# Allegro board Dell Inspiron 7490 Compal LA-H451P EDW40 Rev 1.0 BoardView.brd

Outline 215.71 x 81.8 mm; copper layers: TOP, GND1, IN1, GND2, VCC, IN2, GND3, IN3, GND4, BOTTOM. Coordinates in mm from the lower left corner of the outline.
Outline path: circle c80.48,25.78 r0.65 ; 0,29.9 0,15.1 0.6,14.5 0.6,0 16.6,0 arc(17.19,1.41) 18.6,2 27.15,2 27.15,3 arc(27.3,3.35) 27.65,3.5 29.45,3.5 arc(29.8,3.35) 29.95,3 29.95,2 46.15,2 46.15,3 arc(46.3,3.35) 46.65,3.5 48.45,3.5 arc(48.8,3.35) 48.95,3 48.95,2 215.71,2 215.71,5.2 214.95,5.2 arc(213.15,7) 214.95,8.8 215.71,8.8 215.71,17.38 arc(213.29,21.9) 211.59,26.73 206.19,46.9 203.75,46.9 arc(201.65,49) 203.75,51.1 205.06,51.1 200.21,69.21 200.21,81.8 165.35,81.8 165.35,81 arc(165.2,80.65) 164.85,80.5 163.05,80.5 arc(162.7,80.65) 162.55,81 162.55,81.8 75.45,81.8 75.45,81 arc(75.3,80.65) 74.95,80.5 73.15,80.5 arc(72.8,80.65) 72.65,81 72.65,81.8 49.95,81.8 49.95,81 arc(49.8,80.65) 49.45,80.5 47.65,80.5 arc(47.3,80.65) 47.15,81 47.15,81.8 24.4,81.8 20.6,78 0.6,78 0.6,70.65 5.96,70.65 arc(6.46,71.14) 6.96,70.65 6.96,61.35 arc(6.46,60.85) 5.96,61.35 1.36,61.35 arc(0.99,60.89) 0.82,60.32 arc(0.72,60.13) 0.52,60.05 0.4,60.05 arc(0.19,59.96) 0.1,59.75 0.1,59.45 arc(0.19,59.24) 0.4,59.15 1.25,59.15 arc(1.6,59) 1.75,58.65 1.75,54.45 arc(1.66,54.24) 1.45,54.15 0.6,54.15 arc(0.39,54.06) 0.3,53.85 0.3,52.75 arc(0.39,52.54) 0.6,52.45 1.2,52.45 arc(1.41,52.36) 1.5,52.15 1.5,51.25 10.31,51.25 arc(10.81,50.75) 10.31,50.25 10.31,36.75 arc(10.81,36.25) 10.31,35.75 0.6,35.75 0.6,30.5 0,29.9 ; 11.25,76.9 arc(11.6,77.25) 11.95,76.9 11.95,74.1 arc(11.6,73.75) 11.25,74.1 11.25,76.9 ; 11.25,57.9 arc(11.6,58.25) 11.95,57.9 11.95,55.1 arc(11.6,54.75) 11.25,55.1 11.25,57.9 ; 115.4,79.3 arc(115.49,79.51) 115.7,79.6 116,79.6 arc(116.21,79.51) 116.3,79.3 116.3,78 arc(116.21,77.79) 116,77.7 115.7,77.7 arc(115.49,77.79) 115.4,78 115.4,79.3

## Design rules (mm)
constraint set DEFAULT: min track width 0.081
net group CLK_ITPXDP_: nets CLK_ITPXDP_N CLK_ITPXDP_P
net group CLK_ITPXDP__R: nets CLK_ITPXDP_N_R CLK_ITPXDP_P_R
net group CLK_TP_SIO_I2C_DAT: nets CLK_TP_SIO_I2C_DAT DAT_TP_SIO_I2C_CLK
net group DIFFPAIR0: nets DDR_M1_CLK0 DDR_M1_CLK#0
net group DIFFPAIR1: nets DDR_M1_DQS7 DDR_M1_DQS#7
net group DIFFPAIR2: nets DDR_M0_DQS5 DDR_M0_DQS#5
net group DIFFPAIR3: nets DDR_M0_DQS4 DDR_M0_DQS#4
net group DIFFPAIR4: nets DDR_M0_DQS1 DDR_M0_DQS#1
net group DIFFPAIR5: nets DDR_M0_DQS0 DDR_M0_DQS#0
net group DIFFPAIR6: nets DDR_M0_DQS3 DDR_M0_DQS#3
net group DIFFPAIR7: nets DDR_M1_DQS6 DDR_M1_DQS#6
net group DIFFPAIR8: nets DDR_M1_DQS3 DDR_M1_DQS#3
net group DIFFPAIR9: nets DDR_M1_DQS2 DDR_M1_DQS#2
net group DIFFPAIR10: nets DDR_M0_DQS7 DDR_M0_DQS#7
net group DIFFPAIR11: nets DDR_M0_DQS6 DDR_M0_DQS#6
net group DIFFPAIR12: nets DDR_M0_DQS2 DDR_M0_DQS#2
net group DIFFPAIR13: nets DDR_M1_DQS0 DDR_M1_DQS#0
net group DIFFPAIR14: nets DDR_M1_DQS1 DDR_M1_DQS#1
net group DIFFPAIR15: nets DDR_M1_DQS4 DDR_M1_DQS#4
net group DIFFPAIR16: nets DDR_M1_DQS5 DDR_M1_DQS#5
net group DIFFPAIR34: nets DDR_M0_CLK1 DDR_M0_CLK#1
net group DIFFPAIR35: nets DDR_M0_CLK0 DDR_M0_CLK#0
net group DIFFPAIR36: nets DDR_M1_CLK1 DDR_M1_CLK#1
net group DIFFPAIR37: nets XTAL_IN XTAL_OUT
net group DIFFPAIR53: nets NCT7718_DXN NCT7718_DXP
net group DIFFPAIR54: nets PRB12_CSON PRB12_CSOP
net group DIFFPAIR55: nets PRB01_CSIN PRB01_CSIP
net group DIFFPAIR56: nets GND_SENSE_GPU VDD_SENSE_GPU
net group DIFFPAIR57: nets DMIC_CLK_EDP DMIC_DATA_EDP
net group DIFFPAIR58: nets PBAT_CHARGER_SMBCLK PBAT_CHARGER_SMBDAT
net group DIFFPAIR59: nets TBT_DP1_N3_R TBT_DP1_P3_R
net group DIFFPAIR60: nets TBT_DP1_N2_R TBT_DP1_P2_R
net group DIFFPAIR61: nets TBT_DP1_N1_R TBT_DP1_P1_R
net group DIFFPAIR62: nets TBT_DP1_N0_R TBT_DP1_P0_R
net group LED: nets AMBER_LED_BAT WHITE_LED_BAT
net group SMB: nets GPU_THM_SMBCLK GPU_THM_SMBDAT
net group ASY: nets ALL_SYS_PWRGD CATERR# H_CPUPWRGD H_PROCHOT# H_PROCHOT#_R H_THERMTRIP# PECI_EC RUNPWROK SCLK_CPU SDIO_CPU VCCST_PWRGD VIDALERT# VIDSCLK VIDSOUT
net group AUDIO: nets DMIC_CLK0 DMIC_CLK_CODEC DMIC_DATA0 DMIC_DATA_CODEC
net group CARD: nets SD_WP
net group CLK: nets REFCLK_CNV REFCLK_CNV_L REFCLK_CNV_R XCLK_BIASREF XTAL_OUTBUFF XTAL_SSIN
net group CLK_RT-24M: nets PCH_RTCX1 PCH_RTCX2 XTAL24_IN XTAL24_IN_R XTAL24_OUT XTAL24_OUT_R
net group CNVI_12_15: nets CLK_CNV_CRX_DTX_N CLK_CNV_CRX_DTX_P CLK_CNV_CRX_R_DTX_N CLK_CNV_CRX_R_DTX_P CLK_CNV_CTX_DRX_N CLK_CNV_CTX_DRX_P CLK_CNV_CTX_R_DRX_N CLK_CNV_CTX_R_DRX_P CNV_CRX_DTX_N0 CNV_CRX_DTX_N1 CNV_CRX_DTX_P0 CNV_CRX_DTX_P1 CNV_CRX_R_DTX_N0 CNV_CRX_R_DTX_N1 CNV_CRX_R_DTX_P0 CNV_CRX_R_DTX_P1 CNV_CTX_DRX_N0 CNV_CTX_DRX_N1 CNV_CTX_DRX_P0 CNV_CTX_DRX_P1 CNV_CTX_R_DRX_N0 CNV_CTX_R_DRX_N1 CNV_CTX_R_DRX_P0 CNV_CTX_R_DRX_P1
net group CNVIRGI-BRI_5_15: nets CNV_BRI_CRX_DTX CNV_BRI_CRX_R_DTX CNV_BRI_CTX_DRX CNV_BRI_CTX_R_DRX CNV_RGI_CRX_DTX CNV_RGI_CRX_R_DTX CNV_RGI_CTX_DRX CNV_RGI_CTX_R_DRX
net group CPU_SPI: nets CPU_SPI_0_CLK CPU_SPI_0_CS#0 CPU_SPI_0_CS#1 CPU_SPI_0_D0 CPU_SPI_0_D1 CPU_SPI_0_D2 CPU_SPI_0_D3 CPU_SPI_CLK CPU_SPI_D0 CPU_SPI_D1 CPU_SPI_D2 CPU_SPI_D3 SPI_CLK_ROM SPI_D0_ROM SPI_D1_ROM SPI_D2_ROM SPI_D3_ROM
net group DDRA_CKE: nets DDR_M0_CKE0 DDR_M0_CKE1 DDR_M0_CKE2 DDR_M0_CKE3
net group DDRA_CMD: nets DDR_M0_CAA_0 DDR_M0_CAA_1 DDR_M0_CAA_2 DDR_M0_CAA_3 DDR_M0_CAA_4 DDR_M0_CAA_5 DDR_M0_CAA_6 DDR_M0_CAA_7 DDR_M0_CAA_8 DDR_M0_CAA_9 DDR_M0_CAB_0 DDR_M0_CAB_1 DDR_M0_CAB_2 DDR_M0_CAB_3 DDR_M0_CAB_4 DDR_M0_CAB_5 DDR_M0_CAB_6 DDR_M0_CAB_7 DDR_M0_CAB_8 DDR_M0_CAB_9
net group DDRA_CTRL: nets DDR_M0_CS#0 DDR_M0_CS#1 DDR_M0_ODT0
net group DDRA_DS0: nets DDR_M0_D0 DDR_M0_D1 DDR_M0_D2 DDR_M0_D3 DDR_M0_D4 DDR_M0_D5 DDR_M0_D6 DDR_M0_D7
net group DDRA_DS1: nets DDR_M0_D8 DDR_M0_D9 DDR_M0_D10 DDR_M0_D11 DDR_M0_D12 DDR_M0_D13 DDR_M0_D14 DDR_M0_D15
net group DDRA_DS2: nets DDR_M0_D16 DDR_M0_D17 DDR_M0_D18 DDR_M0_D19 DDR_M0_D20 DDR_M0_D21 DDR_M0_D22 DDR_M0_D23
net group DDRA_DS3: nets DDR_M0_D24 DDR_M0_D25 DDR_M0_D26 DDR_M0_D27 DDR_M0_D28 DDR_M0_D29 DDR_M0_D30 DDR_M0_D31
net group DDRA_DS4: nets DDR_M0_D32 DDR_M0_D33 DDR_M0_D34 DDR_M0_D35 DDR_M0_D36 DDR_M0_D37 DDR_M0_D38 DDR_M0_D39
net group DDRA_DS5: nets DDR_M0_D40 DDR_M0_D41 DDR_M0_D42 DDR_M0_D43 DDR_M0_D44 DDR_M0_D45 DDR_M0_D46 DDR_M0_D47
net group DDRA_DS6: nets DDR_M0_D48 DDR_M0_D49 DDR_M0_D50 DDR_M0_D51 DDR_M0_D52 DDR_M0_D53 DDR_M0_D54 DDR_M0_D55
net group DDRA_DS7: nets DDR_M0_D56 DDR_M0_D57 DDR_M0_D58 DDR_M0_D59 DDR_M0_D60 DDR_M0_D61 DDR_M0_D62 DDR_M0_D63
net group DDRB_CKE: nets DDR_M1_CKE0 DDR_M1_CKE1 DDR_M1_CKE2 DDR_M1_CKE3
net group DDRB_CMD: nets DDR_M1_CAA_0 DDR_M1_CAA_1 DDR_M1_CAA_2 DDR_M1_CAA_3 DDR_M1_CAA_4 DDR_M1_CAA_5 DDR_M1_CAA_6 DDR_M1_CAA_7 DDR_M1_CAA_8 DDR_M1_CAA_9 DDR_M1_CAB_0 DDR_M1_CAB_1 DDR_M1_CAB_2 DDR_M1_CAB_3 DDR_M1_CAB_4 DDR_M1_CAB_5 DDR_M1_CAB_6 DDR_M1_CAB_7 DDR_M1_CAB_8 DDR_M1_CAB_9
net group DDRB_CTRL: nets DDR_M1_CS#0 DDR_M1_CS#1 DDR_M1_ODT0
net group DDRB_DS0: nets DDR_M1_D0 DDR_M1_D1 DDR_M1_D2 DDR_M1_D3 DDR_M1_D4 DDR_M1_D5 DDR_M1_D6 DDR_M1_D7
net group DDRB_DS1: nets DDR_M1_D8 DDR_M1_D9 DDR_M1_D10 DDR_M1_D11 DDR_M1_D12 DDR_M1_D13 DDR_M1_D14 DDR_M1_D15
net group DDRB_DS2: nets DDR_M1_D16 DDR_M1_D17 DDR_M1_D18 DDR_M1_D19 DDR_M1_D20 DDR_M1_D21 DDR_M1_D22 DDR_M1_D23
net group DDRB_DS3: nets DDR_M1_D24 DDR_M1_D25 DDR_M1_D26 DDR_M1_D27 DDR_M1_D28 DDR_M1_D29 DDR_M1_D30 DDR_M1_D31
net group DDRB_DS4: nets DDR_M1_D32 DDR_M1_D33 DDR_M1_D34 DDR_M1_D35 DDR_M1_D36 DDR_M1_D37 DDR_M1_D38 DDR_M1_D39
net group DDRB_DS5: nets DDR_M1_D40 DDR_M1_D41 DDR_M1_D42 DDR_M1_D43 DDR_M1_D44 DDR_M1_D45 DDR_M1_D46 DDR_M1_D47
net group DDRB_DS6: nets DDR_M1_D48 DDR_M1_D49 DDR_M1_D50 DDR_M1_D51 DDR_M1_D52 DDR_M1_D53 DDR_M1_D54 DDR_M1_D55
net group DDRB_DS7: nets DDR_M1_D56 DDR_M1_D57 DDR_M1_D58 DDR_M1_D59 DDR_M1_D60 DDR_M1_D61 DDR_M1_D62 DDR_M1_D63
net group DP: nets CPU_DP1_AUXN CPU_DP1_AUXN_C CPU_DP1_AUXP CPU_DP1_AUXP_C CPU_DP1_CTRL_DATA CPU_DP1_N0 CPU_DP1_N0_C CPU_DP1_N1 CPU_DP1_N1_C CPU_DP1_N2 CPU_DP1_N2_C CPU_DP1_N3 CPU_DP1_N3_C CPU_DP1_P0 CPU_DP1_P0_C CPU_DP1_P1 CPU_DP1_P1_C CPU_DP1_P2 CPU_DP1_P2_C CPU_DP1_P3 CPU_DP1_P3_C CPU_DP2_AUXN CPU_DP2_AUXN_C CPU_DP2_AUXP CPU_DP2_AUXP_C CPU_DP2_CTRL_DATA CPU_DP2_N0 CPU_DP2_N0_C CPU_DP2_N1 CPU_DP2_N1_C CPU_DP2_N2 CPU_DP2_N2_C CPU_DP2_N3 CPU_DP2_N3_C CPU_DP2_P0 CPU_DP2_P0_C CPU_DP2_P1 CPU_DP2_P1_C CPU_DP2_P2 CPU_DP2_P2_C CPU_DP2_P3 CPU_DP2_P3_C
net group EDP: nets EDP_AUXN EDP_AUXN_C EDP_AUXP EDP_AUXP_C EDP_TXN0 EDP_TXN0_C EDP_TXN1 EDP_TXN1_C EDP_TXP0 EDP_TXP0_C EDP_TXP1 EDP_TXP1_C
net group ESPI: nets ESPI_CLK ESPI_CLK_R ESPI_CS# ESPI_IO0 ESPI_IO0_R ESPI_IO1 ESPI_IO1_R ESPI_IO2 ESPI_IO2_R ESPI_IO3 ESPI_IO3_R ESPI_RESET#
net group FB_A_CLK: nets FB_A_CLK0 FB_A_CLK1 FB_A_CLK#0 FB_A_CLK#1
net group FB_A_CMD: nets FB_A_CMD0 FB_A_CMD1 FB_A_CMD2 FB_A_CMD3 FB_A_CMD4 FB_A_CMD5 FB_A_CMD6 FB_A_CMD7 FB_A_CMD8 FB_A_CMD9 FB_A_CMD10 FB_A_CMD11 FB_A_CMD12 FB_A_CMD13 FB_A_CMD14 FB_A_CMD15 FB_A_CMD16 FB_A_CMD17 FB_A_CMD18 FB_A_CMD19 FB_A_CMD20 FB_A_CMD21 FB_A_CMD22 FB_A_CMD23 FB_A_CMD24 FB_A_CMD25 FB_A_CMD26 FB_A_CMD27 FB_A_CMD28 FB_A_CMD29 FB_A_CMD30 FB_A_CMD31
net group FB_A_DBI: nets FB_A_DBI0 FB_A_DBI1 FB_A_DBI2 FB_A_DBI3 FB_A_DBI4 FB_A_DBI5 FB_A_DBI6 FB_A_DBI7
net group FB_A_DSM0: nets FB_A_D0 FB_A_D1 FB_A_D2 FB_A_D3 FB_A_D4 FB_A_D5 FB_A_D6 FB_A_D7
net group FB_A_DSM1: nets FB_A_D8 FB_A_D9 FB_A_D10 FB_A_D11 FB_A_D12 FB_A_D13 FB_A_D14 FB_A_D15
net group FB_A_DSM2: nets FB_A_D16 FB_A_D17 FB_A_D18 FB_A_D19 FB_A_D20 FB_A_D21 FB_A_D22 FB_A_D23
net group FB_A_DSM3: nets FB_A_D24 FB_A_D25 FB_A_D26 FB_A_D27 FB_A_D28 FB_A_D29 FB_A_D30 FB_A_D31
net group FB_A_DSM4: nets FB_A_D32 FB_A_D33 FB_A_D34 FB_A_D35 FB_A_D36 FB_A_D37 FB_A_D38 FB_A_D39
net group FB_A_DSM5: nets FB_A_D40 FB_A_D41 FB_A_D42 FB_A_D43 FB_A_D44 FB_A_D45 FB_A_D46 FB_A_D47
net group FB_A_DSM6: nets FB_A_D48 FB_A_D49 FB_A_D50 FB_A_D51 FB_A_D52 FB_A_D53 FB_A_D54 FB_A_D55
net group FB_A_DSM7: nets FB_A_D56 FB_A_D57 FB_A_D58 FB_A_D59 FB_A_D60 FB_A_D61 FB_A_D62 FB_A_D63
net group FB_A_EDC: nets FB_A_EDC0 FB_A_EDC1 FB_A_EDC2 FB_A_EDC3 FB_A_EDC4 FB_A_EDC5 FB_A_EDC6 FB_A_EDC7
net group FB_A_WCK: nets FB_A_WCK0 FB_A_WCK1 FB_A_WCK2 FB_A_WCK3 FB_A_WCK#0 FB_A_WCK#1 FB_A_WCK#2 FB_A_WCK#3
net group FB_VREF: nets FB_VREF
net group HDA: nets HDA_BIT_CLK HDA_BIT_CLK_R HDA_SDIN0 HDA_SDOUT HDA_SDOUT_R HDA_SYNC HDA_SYNC_R
net group HDMI: nets TMDS_T_TX0N TMDS_T_TX0N_R TMDS_T_TX0P TMDS_T_TX0P_R TMDS_T_TX1N TMDS_T_TX1N_R TMDS_T_TX1P TMDS_T_TX1P_R TMDS_T_TX2N TMDS_T_TX2N_R TMDS_T_TX2P TMDS_T_TX2P_R TMDS_T_TXCN TMDS_T_TXCN_R TMDS_T_TXCP TMDS_T_TXCP_R
net group I2C: nets DDC_SCL_HDMI DDC_SDA_HDMI I2C1_PD_L_CLK I2C1_PD_L_DAT I2C1_PD_L_INT# I2C2_PD_L_CLK I2C2_PD_L_DAT I2C2_PD_L_INT# I2C_0_SCL I2C_0_SDA I2C_1_SCL I2C_1_SDA I2CB_SCL I2CB_SDA I2CC_SCL I2CC_SDA I2CS_SCL I2CS_SDA ISH_I2C_0_SCL ISH_I2C_0_SDA ISH_I2C_1_SCL ISH_I2C_1_SDA PS_SMBCLK PS_SMBDAT TBT_I2C_SCL TBT_I2C_SDA TBTA_I2C_INT#
net group KB: nets KSI0 KSI1 KSI2 KSI3 KSI4 KSI5 KSI6 KSI7 KSO10 KSO11 KSO12 KSO13 KSO14 KSO15 KSO16
net group PCIE: nets PCIE_CRX_C_DTX_N13 PCIE_CRX_C_DTX_N14 PCIE_CRX_C_DTX_N15 PCIE_CRX_C_DTX_N16 PCIE_CRX_C_DTX_P13 PCIE_CRX_C_DTX_P14 PCIE_CRX_C_DTX_P15 PCIE_CRX_C_DTX_P16 PCIE_CRX_DTX_N1 PCIE_CRX_DTX_N9 PCIE_CRX_DTX_N10 PCIE_CRX_DTX_N11 PCIE_CRX_DTX_N12 PCIE_CRX_DTX_N13 PCIE_CRX_DTX_N15 PCIE_CRX_DTX_N16 PCIE_CRX_DTX_P1 PCIE_CRX_DTX_P9 PCIE_CRX_DTX_P10 PCIE_CRX_DTX_P11 PCIE_CRX_DTX_P12 PCIE_CRX_DTX_P13 PCIE_CRX_DTX_P15 PCIE_CRX_DTX_P16 PCIE_CRX_L_DTX_N1 PCIE_CRX_L_DTX_P1 PCIE_CTX_C_DRX_N1 PCIE_CTX_C_DRX_N9 PCIE_CTX_C_DRX_N10 PCIE_CTX_C_DRX_N11 PCIE_CTX_C_DRX_N12 PCIE_CTX_C_DRX_N13 PCIE_CTX_C_DRX_N14 PCIE_CTX_C_DRX_N15 PCIE_CTX_C_DRX_N16 PCIE_CTX_C_DRX_P1 PCIE_CTX_C_DRX_P9 PCIE_CTX_C_DRX_P10 PCIE_CTX_C_DRX_P11 PCIE_CTX_C_DRX_P12 PCIE_CTX_C_DRX_P13 PCIE_CTX_C_DRX_P14 PCIE_CTX_C_DRX_P15 PCIE_CTX_C_DRX_P16 PCIE_CTX_DRX_N1 PCIE_CTX_DRX_N9 PCIE_CTX_DRX_N10 PCIE_CTX_DRX_N11 PCIE_CTX_DRX_N12 PCIE_CTX_DRX_N13 PCIE_CTX_DRX_N14 PCIE_CTX_DRX_N15 PCIE_CTX_DRX_N16 PCIE_CTX_DRX_P1 PCIE_CTX_DRX_P9 PCIE_CTX_DRX_P10 PCIE_CTX_DRX_P11 PCIE_CTX_DRX_P12 PCIE_CTX_DRX_P13 PCIE_CTX_DRX_P14 PCIE_CTX_DRX_P15 PCIE_CTX_DRX_P16 PCIE_CTX_L_DRX_N1 PCIE_CTX_L_DRX_P1
net group PD: nets +VCC1V8_TBT_L_LDO +VCC3V3_TBT_L_LDO +VIN_3V3_L_TBT MUX_L_FLIP#_R PD_EE_CLK_L PD_EE_CS#_L PD_EE_MISO_L PD_EE_MOSI_L PD_L_DDM_MUX1_EN_R PD_L_GPIO2 PD_L_GPIO4 PD_L_GPIO16 PD_L_GPIO17 PD_L_USB_MUX1_EN_R RESET_N TBT_L_FORCE_PWR TBTA_CC1 TBTA_CC2 TBTA_HPD_R
net group PEG: nets PCIE_CRX_DTX_N14 PCIE_CRX_DTX_P14 PEG_CRX_C_GTX_N5 PEG_CRX_C_GTX_N6 PEG_CRX_C_GTX_N7 PEG_CRX_C_GTX_N8 PEG_CRX_C_GTX_P5 PEG_CRX_C_GTX_P6 PEG_CRX_C_GTX_P7 PEG_CRX_C_GTX_P8 PEG_CRX_GTX_N5 PEG_CRX_GTX_N6 PEG_CRX_GTX_N7 PEG_CRX_GTX_N8 PEG_CRX_GTX_P5 PEG_CRX_GTX_P6 PEG_CRX_GTX_P7 PEG_CRX_GTX_P8 PEG_CTX_C_GRX_N5 PEG_CTX_C_GRX_N6 PEG_CTX_C_GRX_N7 PEG_CTX_C_GRX_N8 PEG_CTX_C_GRX_P5 PEG_CTX_C_GRX_P6 PEG_CTX_C_GRX_P7 PEG_CTX_C_GRX_P8 PEG_CTX_GRX_N5 PEG_CTX_GRX_N6 PEG_CTX_GRX_N7 PEG_CTX_GRX_N8 PEG_CTX_GRX_P5 PEG_CTX_GRX_P6 PEG_CTX_GRX_P7 PEG_CTX_GRX_P8
net group PLATFORM CLK_8/12_12/15: nets CLK_PCIE_N2 CLK_PCIE_N2_R CLK_PCIE_N3 CLK_PCIE_N4 CLK_PCIE_P2 CLK_PCIE_P2_R CLK_PCIE_P3 CLK_PCIE_P4 CLK_PEG_N0 CLK_PEG_P0 CLKREQ_CNV# CLKREQ_CNV#_R CLKREQ_PCIE#2 CLKREQ_PCIE#2_R CLKREQ_PCIE#3 CLKREQ_PCIE#4 CLKREQ_PEG#0
net group PWR: nets +0.6V_DDR_VTT +0.6VSP +1.0VS_DGPU +1.2V_DDR +1.05V_MPHYPLL +1.05V_VCCDSW +1.05V_XTAL +1.8VALW_EC +1.8VS +1.8VS_DGPU_AON +1.8VS_DGPU_MAIN +1.8VU +1.35VS_VRAM +3.3V_WLAN +3V_DVDD +3V_HDA +3VALWP +3VLP +3VS_CR +3VS_SSD +5V_KB_BL +5VALWP +5VS +FB_PLLAVDD +GPU_PLLVDD +LCDVDD_LCD +MIC_VCC +PEX_IOVDDQ +PEX_PLL_HVDD +RTC_CELL_VBAT +RTC_SOC +RTC_VCC +TP_VDD +TS_VDD +VCCLDOSRAM_1P24 +VCCPLL_OC +VCCST +VCCSTG
net group PWR_M: nets PCH_PWROK PCH_RSMRST#_Q PCIE_WAKE# SIO_PWRBTN# SYS_RESET# XDP_PWRBTN#
net group RCOMP: nets CFG_RCOMP CNV_WT_RCOMP CPU_POPIRCOMP EDP_COMP EMMC_RCOMP PCH_POPIRCOMP PCIE_RCOMPN PCIE_RCOMPP SD_RCOMP USB2_COMP
net group RCOMP_SM: nets SM_RCOMP0 SM_RCOMP1 SM_RCOMP2
net group RTC: nets PCH_RTCRST# PCH_SRTCRST# SUSCLK SUSCLK_WLAN SUSCLK_WWAN
net group S7/5/6/5: nets CFG0 CFG1 CFG2 CFG3 CFG4 CFG5 CFG6 CFG7 CFG8 CFG9 CFG10 CFG11 CFG12 CFG13 CFG14 CFG15 CPU_XDP_TMS
net group S10: nets SDIO_0_CLK_R
net group S10/8: nets CFG16 CFG17 CFG18 CFG19 CPU_XDP_TCK
net group SDIO: nets SDIO_0_CD#
net group SDXC: nets SDIO_0_CLK SDIO_0_CMD SDIO_0_DATA0 SDIO_0_DATA0_R SDIO_0_DATA1_R SDIO_0_DATA2 SDIO_0_DATA2_R SDIO_0_DATA3 SDIO_0_DATA3_R
net group SENSE: nets USB2_VBUSSENSE VCC_GT_SENSE VCCSENSE VSA_SEN+ VSA_SEN- VSS_GT_SENSE VSSSENSE
net group SMBUS: nets CLK_SMB DAT_SMB MEM_SMBCLK MEM_SMBDATA SML0_SMBCLK SML0_SMBDATA THM_SML1_CLK THM_SML1_DATA TYPEC_SMBCLK TYPEC_SMBDA UPD1_SMBINT#
net group SYS_M: nets INTRUDER#
net group TBT: nets TBT_A_SBU1 TBT_A_SBU2 TBT_A_TRX_DTX_N1 TBT_A_TRX_DTX_N2 TBT_A_TRX_DTX_P1 TBT_A_TRX_DTX_P2 TBT_A_TTX_C_DRX_N1 TBT_A_TTX_C_DRX_N2 TBT_A_TTX_C_DRX_P1 TBT_A_TTX_C_DRX_P2 TBT_A_TTX_DRX_N1 TBT_A_TTX_DRX_N2 TBT_A_TTX_DRX_P1 TBT_A_TTX_DRX_P2
net group TBT_DP: nets TBT_DP1_AUXN TBT_DP1_AUXN_C TBT_DP1_AUXP TBT_DP1_AUXP_C TBT_DP1_N0 TBT_DP1_N0_C TBT_DP1_N1 TBT_DP1_N1_C TBT_DP1_N2 TBT_DP1_N2_C TBT_DP1_N3 TBT_DP1_N3_C TBT_DP1_P0 TBT_DP1_P0_C TBT_DP1_P1 TBT_DP1_P1_C TBT_DP1_P2 TBT_DP1_P2_C TBT_DP1_P3 TBT_DP1_P3_C
net group USB2.0: nets SW_USB20_1_N3 SW_USB20_1_N3_R SW_USB20_1_P3 SW_USB20_1_P3_R SW_USB20_2_N3 SW_USB20_2_N3_R SW_USB20_2_P3 SW_USB20_2_P3_R USB20_N1 USB20_N1_R USB20_N2 USB20_N2_R USB20_N3 USB20_N5 USB20_N5_R USB20_N6 USB20_N6_R USB20_P1 USB20_P1_R USB20_P2 USB20_P2_R USB20_P3 USB20_P5 USB20_P5_R USB20_P6 USB20_P6_R
net group USB3.1: nets USB3_CRX_DTX_N3 USB3_CRX_DTX_N4 USB3_CRX_DTX_P3 USB3_CRX_DTX_P4 USB3_CTX_DRX_N3 USB3_CTX_DRX_N4 USB3_CTX_DRX_P3 USB3_CTX_DRX_P4
net group XDP: nets USB_OC0# USB_OC1# USB_OC2# USB_OC3# XDP_ITP_PMODE
net group XTALIN: nets XTAL_OUT_R
nets with their own width: min track width 0.076; nets GND
nets with their own width: min track width 0.254; nets AMBER_LED_BAT_R WHITE_LED_BAT_R
nets with their own width: min track width 0.508; nets +V_DDR_REF_CA +V_DDR_REFA_R +V_DDR_REFB_R +VREFCA +VREFDQ_A +VREFDQ_B

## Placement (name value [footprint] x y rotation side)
C2  22P_0201_25V8  [C_0201]  58.97 22.43 270 top
C3  1U_0201_6.3V6M  [C_0201]  60.62 26.07 180 top
C4  0.1U_0201_16V6K  [C_0201]  94.3 11.55 270 bottom
C7  0.1U_0201_25V6K  [C_0201]  37.87 70.09 180 top
C8  1U_0201_6.3V6M  [C_0201]  38.46 70.09 0 top
C9  12P_0201_25V8J  [C_0201]  37.87 71.21 180 top
C12  0.1U_0201_16V6K  [C_0201]  21.6 72.06 0 top
C13  0.1U_0201_16V6K  [C_0201]  21.6 71.49 0 top
C14  0.1U_0201_16V6K  [C_0201]  21.6 73.67 0 top
C15  0.1U_0201_16V6K  [C_0201]  21.6 73.08 0 top
C16  1U_0201_6.3V6M  [C_0201]  45.44 56.96 90 top
C17  0.1U_0201_16V6K  [C_0201]  28.06 71.59 90 top
C19  0.1U_0201_16V6K  [C_0201]  27.5 71.59 90 top
C22  0.1U_0201_16V6K  [C_0201]  40.58 9.99 0 bottom
C23  0.1U_0201_10V6K  [C_0201]  117.91 11.54 0 top
C26  0.1U_0201_10V6K  [C_0201]  124 12.7 180 bottom
C28  0.1U_0201_16V6K  [C_0201]  134.8 49.83 90 top
C29  470P_0201_25V7K  [C_0201]  198.03 31.81 90 bottom
C30  2200P_0201_16V7K  [C_0201]  133.08 50.15 180 top
C36  0.1U_0201_25V6K  [C_0201]  32.08 72.42 270 top
C41  82P_0201_25V8J  [C_0201]  38.46 71.21 0 top
C43  47P_0201_25V8J  [C_0201]  38.46 70.65 0 top
C44  100P_0201_25V7K  [C_0201]  37.87 70.65 180 top
C45  82P_0201_25V8J  [C_0201]  40.21 70.91 180 top
C46  0.1U_0201_25V6K  [C_0201]  40.79 70.91 0 top
C47  47P_0201_25V8J  [C_0201]  40.21 71.46 180 top
C48  100P_0201_25V7K  [C_0201]  40.79 71.46 0 top
C49  10P_0201_25V8  [C_0201]  40.21 70.35 180 top
C50  82P_0201_25V8J  [C_0201]  31.52 73.67 90 top
C51  0.1U_0201_25V6K  [C_0201]  30.41 73.67 90 top
C52  10P_0201_25V8  [C_0201]  30.97 73.67 90 top
C53  82P_0201_25V8J  [C_0201]  13.97 72.36 180 top
C54  0.1U_0201_25V6K  [C_0201]  13.97 73.48 180 top
C55  10P_0201_25V8  [C_0201]  13.97 72.92 180 top
C56  0.1U_0201_10V6K  [C_0201]  112.04 19.27 0 top
C60  470P_0201_25V7K  [C_0201]  49.36 41.2 180 top
C61  0.1U_0201_10V6K  [C_0201]  50.48 45.61 0 top
C62  0.1U_0201_10V6K  [C_0201]  51.14 44.41 90 top
C78  0.1U_0201_10V6K  [C_0201]  41.04 53.61 0 top
C94  0.1U_0201_10V6K  [C_0201]  19.37 61.32 270 top
C104  68P_0201_25V8  [C_0201]  60.78 10.41 270 bottom
C105  68P_0201_25V8  [C_0201]  34.86 8.31 0 top
C106  68P_0201_25V8  [C_0201]  40.58 10.55 0 bottom
C107  68P_0201_25V8  [C_0201]  123.41 12.14 0 bottom
C1223  0.1U_0201_10V6K  [C_0201]  18.64 75.68 90 top
C1224  0.068U_0402_16V7K  [C_0402]  39.36 74.33 90 top
C6671  12P_0201_25V8J  [C_0201]  78.16 32.49 180 top
C6673  10U_0402_6.3V6M  [C_0402]  40.75 49.8 0 top
C6676  1U_0402_25V6K  [C_0402]  44.64 67.28 0 top
C6677  0.1U_0201_25V6K  [C_0201]  40.79 70.35 0 top
C6901  0.1U_0201_10V6K  [C_0201]  105.88 35.52 90 top
C6904  100P_0201_25V8J  [C_0201]  32.08 73.67 90 top
C6905  100P_0201_25V8J  [C_0201]  13.97 74.04 180 top
C6906  82P_0201_25V8J  [C_0201]  135.37 49.83 90 top
C6907  82P_0201_25V8J  [C_0201]  115.53 9.55 0 top
C6908  82P_0201_25V8J  [C_0201]  114.85 5.51 180 top
CB16  1U_0201_6.3V6M  [C_0201]  25.77 5.78 0 bottom
CC1  0.1U_01005_10V6K  [C_01005]  181.35 48.81 0 bottom
CC3  12P_0201_25V8J  [C_0201]  142.77 56.18 180 top
CC4  0.1U_0201_10V6K  [C_0201]  41.26 11 90 top
CC6  22P_0201_25V8  [C_0201]  147.74 62.13 180 bottom
CC7  1U_0201_6.3V6M  [C_0201]  144.88 60.26 0 bottom
CC8  1U_0201_6.3V6M  [C_0201]  125.66 51.87 270 bottom
CC9  27P_0201_25V8  [C_0201]  135.95 31.87 90 bottom
CC10  27P_0201_25V8  [C_0201]  135.95 31.26 270 bottom
CC11  8.2P_0201_25V7D  [C_0201]  131.12 56.08 90 bottom
CC12  8.2P_0201_25V7D  [C_0201]  131.12 54.17 270 bottom
CC15  1U_0201_6.3V6M  [C_0201]  146.88 41.71 270 top
CC16  0.1U_0201_6.3V6K  [C_0201]  146.26 42.48 90 top
CC17  1U_0201_6.3V6M  [C_0201]  148.94 50.66 0 top
CC18  47U_0805_10V6M  [C_0805]  142.89 42.15 180 top
CC19  1U_0201_6.3V6M  [C_0201]  151.77 37.41 270 top
CC20  10U_0402_6.3V6M  [C_0402]  161.97 49.54 0 top
CC21  10U_0402_6.3V6M  [C_0402]  148.02 46.12 90 top
CC22  10U_0402_6.3V6M  [C_0402]  148.35 47.99 180 top
CC23  10U_0402_6.3V6M  [C_0402]  150.07 49.83 180 top
CC24  10U_0402_6.3V6M  [C_0402]  148.35 48.88 180 top
CC25  10U_0402_6.3V6M  [C_0402]  161.08 49.57 180 top
CC26  1U_0201_6.3V6M  [C_0201]  161.99 51.23 0 top
CC27  1U_0201_6.3V6M  [C_0201]  162.02 50.47 0 top
CC28  1U_0201_6.3V6M  [C_0201]  161.08 50.48 180 top
CC29  1U_0201_6.3V6M  [C_0201]  151.34 50.07 0 top
CC30  1U_0201_6.3V6M  [C_0201]  147.25 45.83 180 top
CC31  1U_0201_6.3V6M  [C_0201]  148.1 45.23 270 top
CC32  1U_0201_6.3V6M  [C_0201]  148.68 45.23 270 top
CC33  1U_0201_6.3V6M  [C_0201]  161.08 51.23 180 top
CC34  22U_0603_6.3V6M  [C_0603]  160.85 60.69 0 bottom
CC35  10U_0402_6.3V6M  [C_0402]  155.37 60.46 0 bottom
CC36  10U_0402_6.3V6M  [C_0402]  156.8 61.71 180 bottom
CC37  10U_0402_6.3V6M  [C_0402]  158.07 60.46 180 bottom
CC38  10U_0402_6.3V6M  [C_0402]  154.37 60.42 90 bottom
CC39  10U_0402_6.3V6M  [C_0402]  153.33 60.42 90 bottom
CC40  10U_0402_6.3V6M  [C_0402]  159.85 61.71 180 bottom
CC41  1U_0201_6.3V6M  [C_0201]  165.31 60.4 90 bottom
CC42  1U_0201_6.3V6M  [C_0201]  154.01 62.03 180 bottom
CC43  1U_0201_6.3V6M  [C_0201]  152.84 62.03 180 bottom
CC44  1U_0201_6.3V6M  [C_0201]  151.66 62.07 180 bottom
CC45  10U_0402_6.3V6M  [C_0402]  166.67 60.52 90 bottom
CC46  10U_0402_6.3V6M  [C_0402]  167.61 60.52 90 bottom
CC47  10U_0402_6.3V6M  [C_0402]  159.85 60.46 180 bottom
CC48  1U_0201_6.3V6M  [C_0201]  145.62 43.76 270 top
CC49  22U_0603_6.3V6M  [C_0603]  143.02 43.82 90 top
CC51  0.1U_0201_6.3V6K  [C_0201]  146.05 48.66 270 top
CC52  1U_0201_6.3V6M  [C_0201]  146.63 48.66 270 top
CC53  1U_0201_6.3V6M  [C_0201]  144.63 36.64 270 top
CC54  47U_0603_6.3V6M  [C_0603]  142.64 37.05 270 top
CC55  1U_0201_6.3V6M  [C_0201]  143.85 46 180 top
CC56  1U_0201_6.3V6M  [C_0201]  130.95 37.19 90 bottom
CC57  47U_0603_6.3V6M  [C_0603]  129.99 36.34 270 bottom
CC58  4.7U_0201_6.3V6M  [C_0201]  141.49 49.16 0 top
CC59  1U_0201_6.3V6M  [C_0201]  145.23 49.9 270 top
CC60  1U_0201_6.3V6M  [C_0201]  145.23 46.3 0 top
CC61  1U_0201_6.3V6M  [C_0201]  129.79 44.59 180 bottom
CC62  1U_0201_6.3V6M  [C_0201]  146.26 44.25 270 top
CC63  1U_0201_6.3V6M  [C_0201]  146.05 49.93 270 top
CC64  1U_0201_6.3V6M  [C_0201]  129.78 45.2 180 bottom
CC65  1U_0201_6.3V6M  [C_0201]  132.57 53.46 90 bottom
CC72  22U_0603_6.3V6M  [C_0603]  147.78 42.47 90 top
CC73  10P_0201_25V8  [C_0201]  130.23 60.89 0 bottom
CC74  0.1U_01005_16V6K  [C_01005]  158.2 33.35 90 bottom
CC75  100P_01005_25V8J  [C_01005]  137.27 41.09 90 top
CC76  100P_01005_25V8J  [C_01005]  181.35 49.29 0 bottom
CC77  2P_0201_25V8B  [C_0201]  147.28 60.4 90 bottom
CC78  2P_0201_25V8B  [C_0201]  149.3 61.19 0 bottom
CC79  82P_0201_50V8J  [C_0201]  129.88 50.99 180 bottom
CC80  82P_0201_50V8J  [C_0201]  128.94 49.81 90 bottom
CC81  0.1U_0201_6.3V6K  [C_0201]  155.18 62.03 180 bottom
CC82  0.1U_0201_6.3V6K  [C_0201]  158.16 61.83 180 bottom
CC83  100P_0201_25V8J  [C_0201]  163.25 60.56 0 bottom
CC84  100P_0201_25V8J  [C_0201]  165.9 60.38 90 bottom
CC85  2.2P_0201_25V8C  [C_0201]  145.66 45.59 180 top
CC86  2.2P_0201_25V8C  [C_0201]  143.51 36.64 270 top
CC87  2.2P_0201_25V8C  [C_0201]  122.64 42.57 0 bottom
CC88  2.2P_0201_25V8C  [C_0201]  145.23 47.11 0 top
CC101  1U_0201_6.3V6M  [C_0201]  131.53 37.2 90 bottom
CC102  1U_0201_6.3V6M  [C_0201]  146.83 44.25 270 top
CC103  1U_0201_6.3V6M  [C_0201]  144.07 36.64 270 top
CC104  1U_0201_6.3V6M  [C_0201]  146.63 49.93 270 top
CC105  0.1U_0201_10V6K  [C_0201]  138.8 11.42 90 top
CC106  0.1U_0201_10V6K  [C_0201]  143.64 10.7 0 top
CC107  0.1U_0201_10V6K  [C_0201]  136.75 11.69 0 top
CC108  0.1U_0201_10V6K  [C_0201]  136.75 12.25 0 top
CC109  0.1U_0201_10V6K  [C_0201]  133.06 12.57 90 top
CC110  22P_0201_25V8  [C_0201]  129.97 57.56 270 bottom
CC111  10P_0201_25V8  [C_0201]  53.93 24.22 90 top
CC112  10P_0201_25V8  [C_0201]  152.76 55.07 270 top
CC113  10P_0201_25V8  [C_0201]  149.27 45.23 270 top
CC114  100P_0201_25V8J  [C_0201]  147.51 45.23 270 top
CC115  10P_0201_25V8  [C_0201]  145.17 41.73 270 top
CC116  100P_0201_25V8J  [C_0201]  145.73 41.72 270 top
CC117  1U_0201_6.3V6M  [C_0201]  146.84 42.48 90 top
CC118  0.1U_0201_6.3V6K  [C_0201]  32.08 70.66 90 top
CC119  100P_0201_25V8J  [C_0201]  152.16 32.88 90 bottom
CC120  100P_0201_25V8J  [C_0201]  167.64 37.5 270 top
CD1  1U_0201_6.3V6M  [C_0201]  193.17 47.23 270 bottom
CD2  10U_0603_6.3V6M  [C_0603]  188.01 72.34 0 bottom
CD3  1U_0201_6.3V6M  [C_0201]  173.55 72.45 180 bottom
CD4  10U_0603_6.3V6M  [C_0603]  194.94 56.81 0 top
CD5  1U_0201_6.3V6M  [C_0201]  190.38 47.23 270 bottom
CD6  10U_0603_6.3V6M  [C_0603]  188.01 69.45 0 bottom
CD7  1U_0201_6.3V6M  [C_0201]  187.83 68.56 0 bottom
CD8  1U_0201_6.3V6M  [C_0201]  173.58 69.07 180 bottom
CD9  10U_0402_6.3V6M  [C_0402]  194.03 61.96 90 bottom
CD10  1U_0201_6.3V6M  [C_0201]  193.73 47.23 270 bottom
CD11  1U_0201_6.3V6M  [C_0201]  189.26 47.23 270 bottom
CD12  1U_0201_6.3V6M  [C_0201]  173.55 73.01 180 bottom
CD13  1U_0201_6.3V6M  [C_0201]  189.82 47.23 270 bottom
CD14  1U_0201_6.3V6M  [C_0201]  173.58 68.51 180 bottom
CD15  10U_0603_6.3V6M  [C_0603]  187.27 47.13 270 bottom
CD16  1U_0201_6.3V6M  [C_0201]  185.15 61.58 90 bottom
CD17  1U_0201_6.3V6M  [C_0201]  185.71 61.58 90 bottom
CD18  1U_0201_6.3V6M  [C_0201]  185.67 56.89 180 top
CD19  1U_0201_6.3V6M  [C_0201]  185.67 57.47 180 top
CD20  0.1U_0201_6.3V6K  [C_0201]  192.09 61.65 90 bottom
CD21  0.1U_0201_6.3V6K  [C_0201]  191.54 61.65 90 bottom
CD22  10U_0603_6.3V6M  [C_0603]  188.18 65.18 270 bottom
CD23  1U_0201_6.3V6M  [C_0201]  173.54 66.68 180 bottom
CD24  1U_0201_6.3V6M  [C_0201]  173.54 66.12 180 bottom
CD25  1U_0201_6.3V6M  [C_0201]  187.88 66.52 0 bottom
CD26  1U_0201_6.3V6M  [C_0201]  187.88 65.94 0 bottom
CD27  0.022U_0201_16V6K  [C_0201]  179.06 61.37 0 bottom
CD41  1U_0201_6.3V6M  [C_0201]  166.67 67.51 0 bottom
CD42  1U_0201_6.3V6M  [C_0201]  137.05 73.05 90 bottom
CD43  10U_0603_6.3V6M  [C_0603]  166.95 68.88 90 bottom
CD44  10U_0603_6.3V6M  [C_0603]  166.92 74.25 90 bottom
CD45  1U_0201_6.3V6M  [C_0201]  166.67 66.95 0 bottom
CD46  1U_0201_6.3V6M  [C_0201]  166.67 68.07 0 bottom
CD47  10U_0603_6.3V6M  [C_0603]  150.84 77.02 0 bottom
CD48  1U_0201_6.3V6M  [C_0201]  137.05 74.83 270 bottom
CD49  1U_0201_6.3V6M  [C_0201]  152.24 68 180 bottom
CD50  1U_0201_6.3V6M  [C_0201]  152.24 68.56 180 bottom
CD51  10U_0603_6.3V6M  [C_0603]  148.56 71.91 90 top
CD52  0.022U_0201_16V6K  [C_0201]  177.35 61.39 90 bottom
CD53  10U_0603_6.3V6M  [C_0603]  177.98 76.96 180 top
CD54  10U_0603_6.3V6M  [C_0603]  190.66 61.75 90 bottom
CD55  1U_0201_6.3V6M  [C_0201]  181.98 76.72 90 bottom
CD56  1U_0201_6.3V6M  [C_0201]  197.71 55.84 0 bottom
CD57  0.1U_0201_6.3V6K  [C_0201]  173.58 70.18 180 bottom
CD58  10U_0603_6.3V6M  [C_0603]  186.08 47.13 270 bottom
CD59  0.047U_0201_10V6K  [C_0201]  183.95 54.57 180 bottom
CD60  0.047U_0201_10V6K  [C_0201]  197.71 55.28 0 bottom
CD61  10U_0603_6.3V6M  [C_0603]  192.98 61.72 90 bottom
CD62  0.047U_0201_10V6K  [C_0201]  181.9 62.41 0 bottom
CD63  1U_0201_6.3V6M  [C_0201]  197.71 56.4 0 bottom
CD64  0.047U_0201_10V6K  [C_0201]  178.95 77.91 180 bottom
CD65  1U_0201_6.3V6M  [C_0201]  178.75 76.73 90 bottom
CD66  1U_0201_6.3V6M  [C_0201]  152.2 61.04 180 bottom
CD67  0.1U_0201_6.3V6K  [C_0201]  137.02 70.66 90 bottom
CD68  0.1U_0201_6.3V6K  [C_0201]  151.66 71.91 0 bottom
CD69  10U_0603_6.3V6M  [C_0603]  158.82 74.17 90 top
CD70  1U_0201_6.3V6M  [C_0201]  161.39 76.74 90 bottom
CD71  1U_0201_6.3V6M  [C_0201]  158.16 76.72 90 bottom
CD73  1U_0201_6.3V6M  [C_0201]  152.24 62.97 180 bottom
CD74  1U_0201_6.3V6M  [C_0201]  143.21 74.34 90 top
CD75  0.047U_0201_10V6K  [C_0201]  161.26 62.96 180 bottom
CD76  1U_0201_6.3V6M  [C_0201]  166.67 65.84 0 bottom
CD77  1U_0201_6.3V6M  [C_0201]  151.66 71.36 0 bottom
CD78  0.1U_0201_6.3V6K  [C_0201]  152.24 69.12 180 bottom
CD79  0.1U_0201_6.3V6K  [C_0201]  152.24 69.68 180 bottom
CD80  1U_0201_6.3V6M  [C_0201]  152.24 64.65 180 bottom
CD81  0.047U_0201_10V6K  [C_0201]  143.05 76.67 90 bottom
CD82  0.047U_0201_10V6K  [C_0201]  158.21 77.93 180 bottom
CD83  1U_0201_6.3V6M  [C_0201]  152.24 65.21 180 bottom
CD84  1U_0201_6.3V6M  [C_0201]  151.66 66.33 0 bottom
CD85  1U_0201_6.3V6M  [C_0201]  166.67 66.39 0 bottom
CD86  10U_0603_6.3V6M  [C_0603]  149.81 70.53 0 top
CD87  1U_0201_6.3V6M  [C_0201]  151.66 65.77 0 bottom
CD88  1U_0201_6.3V6M  [C_0201]  143.77 74.34 90 top
CD89  0.047U_0201_10V6K  [C_0201]  151.66 64.09 0 bottom
CD90  10U_0603_6.3V6M  [C_0603]  166.82 64.96 0 bottom
CD91  1U_0201_6.3V6M  [C_0201]  137.07 66.37 270 bottom
CD100  1U_0201_6.3V6M  [C_0201]  198.3 49.17 180 bottom
CD101  1U_0201_6.3V6M  [C_0201]  198.3 48.61 180 bottom
CD102  1U_0201_6.3V6M  [C_0201]  185.34 77.31 270 bottom
CD103  1U_0201_6.3V6M  [C_0201]  185.9 77.31 270 bottom
CD104  10U_0603_6.3V6M  [C_0603]  169.4 77.06 270 bottom
CD105  1U_0201_6.3V6M  [C_0201]  149.5 77.25 270 bottom
CD106  1U_0201_6.3V6M  [C_0201]  150.06 77.25 270 bottom
CD107  1U_0201_6.3V6M  [C_0201]  164.74 77.32 270 bottom
CD108  1U_0201_6.3V6M  [C_0201]  165.3 77.32 270 bottom
CD109  10U_0603_6.3V6M  [C_0603]  170.98 77.06 270 bottom
CD110  10U_0603_6.3V6M  [C_0603]  173.36 77.06 270 bottom
CD111  10U_0603_6.3V6M  [C_0603]  172.17 77.06 270 bottom
CD113  0.022U_0201_16V6K  [C_0201]  175.44 60.48 90 bottom
CD114  0.1U_0201_6.3V6K  [C_0201]  173.58 69.63 180 bottom
CD115  1U_0201_6.3V6M  [C_0201]  137.07 67.57 270 bottom
CD116  0.1U_0201_6.3V6K  [C_0201]  173.58 70.74 180 bottom
CD117  100P_0201_25V7K  [C_0201]  187.85 71.45 0 bottom
CD118  100P_0201_25V7K  [C_0201]  187.85 70.34 0 bottom
CD119  0.1U_0201_25V6K  [C_0201]  187.83 73.23 0 bottom
CD120  100P_0201_25V7K  [C_0201]  187.83 67.44 0 bottom
CD121  100P_0201_25V7K  [C_0201]  187.83 68 0 bottom
CD122  0.1U_0201_6.3V6K  [C_0201]  151.66 70.8 0 bottom
CD123  100P_0201_25V7K  [C_0201]  137.07 68.23 90 bottom
CD124  100P_0201_25V7K  [C_0201]  137.05 70 270 bottom
CD125  0.1U_0201_25V6K  [C_0201]  137.05 75.54 90 bottom
CD126  100P_0201_25V7K  [C_0201]  137.02 72.44 270 bottom
CD127  100P_0201_25V7K  [C_0201]  151.66 67.44 0 bottom
CD128  100P_0201_25V7K  [C_0201]  152.24 73.59 180 bottom
CD129  0.1U_0201_25V6K  [C_0201]  166.66 73.26 0 bottom
CD130  100P_0201_25V7K  [C_0201]  152.24 66.89 180 bottom
CD131  0.1U_0201_6.3V6K  [C_0201]  166.66 72.7 0 bottom
CD132  100P_0201_25V7K  [C_0201]  166.66 71.58 0 bottom
CD133  100P_0201_25V7K  [C_0201]  166.66 71.02 0 bottom
CD134  100P_0201_25V7K  [C_0201]  186.83 61.58 90 bottom
CD135  0.1U_0201_25V6K  [C_0201]  188.15 47.23 270 bottom
CD136  100P_0201_25V7K  [C_0201]  188.7 47.23 270 bottom
CD137  100P_0201_25V7K  [C_0201]  192.62 47.23 270 bottom
CD138  0.1U_0201_6.3V6K  [C_0201]  190.94 47.23 270 bottom
CD139  100P_0201_25V7K  [C_0201]  192.06 47.23 270 bottom
CD140  10P_0201_25V8  [C_0201]  186.27 61.58 90 bottom
CD141  10P_0201_25V8  [C_0201]  173.54 67.24 180 bottom
CD142  10P_0201_25V8  [C_0201]  152.24 73.03 180 bottom
CD143  10P_0201_25V8  [C_0201]  137.15 65.18 270 bottom
CD144  10P_0201_25V8  [C_0201]  166.66 72.14 0 bottom
CD145  10P_0201_25V8  [C_0201]  151.66 70.24 0 bottom
CD146  10P_0201_25V8  [C_0201]  187.85 70.89 0 bottom
CD147  10P_0201_25V8  [C_0201]  191.5 47.23 270 bottom
CE1  10U_0402_6.3V6M  [C_0402]  53.17 33.96 0 top
CE2  0.1U_0201_10V6K  [C_0201]  52.52 17.15 270 top
CE5  0.1U_0201_10V6K  [C_0201]  40.64 32.94 180 top
CE6  0.1U_0201_10V6K  [C_0201]  41.44 17.2 270 top
CE7  0.1U_0201_10V6K  [C_0201]  38.79 25.99 0 top
CE8  0.1U_0201_10V6K  [C_0201]  54.45 25.99 270 top
CE9  0.1U_0201_10V6K  [C_0201]  37.25 22.17 0 top
CE10  0.1U_0201_10V6K  [C_0201]  48.14 16.9 270 top
CE11  0.1U_0201_10V6K  [C_0201]  48.79 16.86 270 top
CE12  0.1U_0402_10V7K  [C_0402]  39.34 20.2 180 top
CE13  0.1U_0201_10V6K  [C_0201]  52.58 19.85 0 top
CE14  2.2U_0201_6.3V6M  [C_0201]  36.54 20.74 180 top
CE15  0.1U_0201_10V6K  [C_0201]  45.45 31.64 90 top
CE16  0.047U_0402_16V4Z  [C_0402]  47.66 31.75 90 top
CE18  0.1U_0201_10V6K  [C_0201]  43.81 35.55 0 top
CE21  0.1U_0201_10V6K  [C_0201]  49.17 18.42 270 top
CE22  0.1U_0201_10V6K  [C_0201]  55.6 20.06 180 top
CE23  1U_0402_16V6K  [C_0402]  43.38 17.5 270 top
CE24  100P_0201_25V8J  [C_0201]  54.44 20.05 270 top
CE26  2200P_0201_25V7K  [C_0201]  46.63 18.16 270 top
CE31  2200P_0201_25V7K  [C_0201]  45.88 18.15 270 top
CE32  100P_0201_25V8J  [C_0201]  38.78 22.14 0 top
CE33  0.1U_0201_16V6K  [C_0201]  3.31 76.47 270 bottom
CE34  10P_0201_25V8  [C_0201]  3.89 74.72 180 bottom
CE36  10U_0402_6.3V6M  [C_0402]  61.74 31.12 90 top
CE100  12P_0201_25V8J  [C_0201]  53.08 32.3 0 top
CE101  100P_0201_25V8J  [C_0201]  53.08 31.68 0 top
CE504  0.1U_0201_10V6K  [C_0201]  49.73 18.42 270 top
CE505  1U_0201_6.3V6M  [C_0201]  44.32 31.89 90 top
CE506  0.1U_0201_10V6K  [C_0201]  44.68 18.23 180 top
CE507  0.1U_0201_10V6K  [C_0201]  44.14 17.63 270 top
CE508  0.1U_0201_6.3V6K  [C_0201]  64.02 24.52 90 top
CE509  100P_0201_25V8J  [C_0201]  46.13 32.34 270 top
CE510  0.01U_0201_10V6K  [C_0201]  31.31 18.77 90 top
CH1  0.01U_01005_10V6K  [C_01005]  19.83 42.6 0 bottom
CIO1  0.1U_0201_6.3V6K  [C_0201]  192.81 9.04 180 top
CIO2  100P_0201_25V8J  [C_0201]  192.81 9.6 180 top
CIO3  1U_0201_6.3V6M  [C_0201]  192.81 8.48 180 top
CIO4  18P_0201_25V8J  [C_0201]  192.81 12.4 180 top
CIO5  2200P_0201_25V7K  [C_0201]  192.81 11.84 180 top
CIO6  8.2P_0201_25V7D  [C_0201]  192.81 12.96 180 top
CIO7  100P_0201_25V8J  [C_0201]  192.81 10.16 180 top
CIO8  100P_0201_25V8J  [C_0201]  192.81 10.72 180 top
CIO9  47P_0201_25V8J  [C_0201]  192.81 11.28 180 top
CLEC1  SHORT PADS  [SHORTPADS]  43.91 33.89 90 top
CLP1  -  [EMIST_SV-11A1M_1P]  54.95 79.6 180 bottom
CLP2  -  [EMIST_SV-11A1M_1P]  63.15 80.4 180 bottom
CLP3  -  [EMIST_SV-11A1M_1P]  86.15 79.6 180 bottom
CLP4  -  [EMIST_SV-11A1M_1P]  98.05 80.4 180 bottom
CLP5  -  [EMIST_SV-11A1M_1P]  108.75 79.6 180 bottom
CLRP2  SHORT PADS  [SHORTPADS]  124.7 51.4 270 bottom
CM1  0.1U_0201_16V6K  [C_0201]  33.69 37.59 90 top
CM2  0.47U_0201_6.3V6K  [C_0201]  20.37 44.18 270 bottom
CM3  10U_0603_6.3V6M  [C_0603]  22.75 42.98 270 bottom
CM4  0.1U_0201_16V6K  [C_0201]  24.91 43.18 0 bottom
CM5  0.1U_0201_16V6K  [C_0201]  24.88 44.3 0 bottom
CM6  0.1U_0201_16V6K  [C_0201]  24.88 43.74 0 bottom
CM10  0.47U_0201_6.3V6K  [C_0201]  25.51 36.44 90 bottom
CM11  10U_0603_6.3V6M  [C_0603]  19.66 40.55 0 bottom
CM12  0.1U_0201_16V6K  [C_0201]  19.71 42.07 0 bottom
CM13  0.1U_0201_16V6K  [C_0201]  19.71 41.46 0 bottom
CM14  0.01U_01005_10V6K  [C_01005]  19.83 43.06 0 bottom
CM15  0.1U_0201_10V6K  [C_0201]  29.42 48.4 315 top
CM16  0.1U_0201_10V6K  [C_0201]  29.03 48 315 top
CM17  0.1U_0201_10V6K  [C_0201]  27.95 48.74 315 top
CM18  0.1U_0201_10V6K  [C_0201]  27.55 48.34 315 top
CM19  0.1U_0201_10V6K  [C_0201]  28.27 47.25 315 top
CM20  0.1U_0201_10V6K  [C_0201]  27.87 46.85 315 top
CM21  0.1U_0201_10V6K  [C_0201]  26.79 47.62 315 top
CM22  0.1U_0201_10V6K  [C_0201]  26.4 47.22 315 top
CM23  0.1U_0201_10V6K  [C_0201]  26.12 36.55 90 top
CM24  0.1U_0201_10V6K  [C_0201]  25.56 36.55 90 top
CM25  0.47U_0201_6.3V6K  [C_0201]  24.4 36.44 90 bottom
CM26  10U_0603_6.3V6M  [C_0603]  16.47 43.05 90 bottom
CM27  0.1U_0201_16V6K  [C_0201]  17.38 43.68 90 bottom
CM28  0.01U_01005_10V6K  [C_01005]  17.92 43.83 90 bottom
CM29  6.8P_0201_25V8B  [C_0201]  19.38 46.36 270 bottom
CM30  6.8P_0201_25V8B  [C_0201]  19.38 47 90 bottom
CM31  0.47U_0201_6.3V6K  [C_0201]  23.84 36.44 90 bottom
CM32  10U_0603_6.3V6M  [C_0603]  23.06 38.24 0 bottom
CM33  0.1U_0201_16V6K  [C_0201]  21.86 40.22 90 bottom
CM34  0.1U_0201_16V6K  [C_0201]  22.42 40.22 90 bottom
CM35  0.1U_0201_16V6K  [C_0201]  22.98 40.22 90 bottom
CM36  0.01U_01005_10V6K  [C_01005]  25.15 39.74 0 bottom
CM37  0.01U_01005_10V6K  [C_01005]  25.15 39.29 0 bottom
CM38  0.01U_01005_10V6K  [C_01005]  25.15 38.83 0 bottom
CM40  0.1U_0201_16V6K  [C_0201]  14.83 55.3 90 top
CM41  0.47U_0201_6.3V6K  [C_0201]  24.95 36.44 90 bottom
CM42  10U_0603_6.3V6M  [C_0603]  18.63 40.55 180 bottom
CM43  0.1U_0201_16V6K  [C_0201]  18.21 42.04 180 bottom
CM44  0.1U_0201_16V6K  [C_0201]  18.21 41.43 180 bottom
CM45  0.01U_01005_10V6K  [C_01005]  18.09 43.03 180 bottom
CM46  0.01U_01005_10V6K  [C_01005]  18.09 42.57 180 bottom
CM47  0.1U_0201_25V6K  [C_0201]  18.08 76.26 270 top
CM48  10U_0402_6.3V6M  [C_0402]  26.96 36.23 90 top
CM49  10U_0402_6.3V6M  [C_0402]  33.85 36.38 270 top
CM50  0.01U_0201_10V6K  [C_0201]  28.25 36.81 270 top
CM51  1U_0201_6.3V6M  [C_0201]  22.28 43.79 0 bottom
CM52  0.22U_0201_6.3V6K  [C_0201]  28.72 54.49 180 top
CN1  22U_0603_6.3V6M  [C_0603]  65.28 45.92 270 top
CN2  0.1U_0201_10V6K  [C_0201]  64.83 49.68 180 top
CN3  33P_0201_50V8J  [C_0201]  64.83 48.01 180 top
CN4  47P_0201_25V8J  [C_0201]  64.83 49.13 180 top
CN5  22U_0603_6.3V6M  [C_0603]  47.14 47.16 0 top
CN6  0.1U_0201_10V6K  [C_0201]  44.9 49.24 180 top
CN7  33P_0201_50V8J  [C_0201]  44.9 49.82 180 top
CN8  47P_0201_25V8J  [C_0201]  47.5 49.81 0 top
CN9  100U_A1_6.3VM_R70M  [C_NEC]  63.65 45.93 270 top
CN10  100U_A1_6.3VM_R70M  [C_NEC]  45.69 47.37 180 top
CN18  0.1U_0201_10V6K  [C_0201]  64.26 51.98 0 top
CN41  0.1U_0201_10V6K  [C_0201]  36.41 69.11 0 bottom
CN57  0.1U_0201_10V6K  [C_0201]  56.45 41.62 270 top
CN58  0.1U_0201_10V6K  [C_0201]  54.28 43.41 0 top
CN59  47P_0201_25V8J  [C_0201]  48.77 60.71 90 bottom
CN60  1U_0201_6.3V6M  [C_0201]  64.83 50.24 180 top
CN61  100P_0201_50V8J  [C_0201]  64.83 50.8 180 top
CN62  18P_0201_50V8J  [C_0201]  64.83 48.57 180 top
CN64  1U_0201_6.3V6M  [C_0201]  47.5 48.06 0 top
CN65  8.2P_0201_25V7D  [C_0201]  64.83 47.45 180 top
CN66  6.8P_0201_25V8B  [C_0201]  44.9 48.65 180 top
CN67  18P_0201_50V8J  [C_0201]  47.5 48.64 0 top
CN68  100P_0201_50V8J  [C_0201]  47.5 49.23 0 top
CN69  8.2P_0201_25V7D  [C_0201]  44.9 50.41 180 top
CN72  0.1U_0201_10V6K  [C_0201]  53.85 51.96 90 top
CN73  0.1U_0201_10V6K  [C_0201]  53.28 51.96 90 top
CPD1  0.1U_0201_10V6K  [C_0201]  28.17 31.64 0 bottom
CPD2  220P_0201_25V7K  [C_0201]  18.7 25.84 180 bottom
CPD3  220P_0201_25V7K  [C_0201]  22.21 25.9 0 bottom
CPD4  10U_0402_10V6M  [C_0402]  28.08 30.36 0 bottom
CPD5  10U_0402_10V6M  [C_0402]  28.27 33.44 0 bottom
CPD6  4.7U_0201_6.3V6M  [C_0201]  15.6 29.9 180 bottom
CPD7  10U_0402_10V6M  [C_0402]  23.74 34.89 180 top
CPD8  22U_0603_6.3V6M  [C_0603]  20 26.19 0 bottom
CPD40  10U_0603_25V6M  [C_0603]  29.45 24 270 bottom
CPD42  1U_0402_25V6K  [C_0402]  29.9 33.67 90 top
CPD47  10U_0603_25V6M  [C_0603]  28.26 24 270 bottom
CPD49  1U_0402_25V6K  [C_0402]  29.04 30.79 270 top
CPD50  68P_0201_25V8  [C_0201]  28.17 31.08 0 bottom
CPD51  68P_0201_25V8  [C_0201]  15.6 29.34 180 bottom
CPD52  68P_0201_25V8  [C_0201]  29.49 29.63 180 bottom
CPD53  68P_0201_25V8  [C_0201]  29.5 35.07 0 bottom
CPD55  10U_0603_25V6M  [C_0603]  31.61 30.05 90 bottom
CPD56  10U_0603_25V6M  [C_0603]  30.39 30.05 90 bottom
CR5  4.7U_0201_6.3V6M  [C_0201]  6.15 31.13 180 top
CR6  0.1U_0201_10V6K  [C_0201]  6.15 30.56 180 top
CR12  100P_0201_25V8J  [C_0201]  5.56 29.99 0 top
CR100  1U_0201_6.3V6M  [C_0201]  9.17 33.1 90 top
CS1  47P_0201_25V8J  [C_0201]  59 49.71 270 top
CS2  2.2P_0201_25V8C  [C_0201]  26.37 6.33 90 top
CS3  0.1U_0201_10V6K  [C_0201]  107.85 35.38 90 top
CS4  1000P_0201_16V7K  [C_0201]  107.29 35.38 90 top
CS5  22U_0603_6.3V6M  [C_0603]  104.96 34.98 90 top
CS6  2.2P_0201_25V8C  [C_0201]  58.45 48.46 270 top
CS7  0.22U_0201_10V6K  [C_0201]  120.33 18.92 180 top
CS8  0.22U_0201_10V6K  [C_0201]  120.33 19.48 180 top
CS9  0.22U_0201_10V6K  [C_0201]  120.26 22.02 180 top
CS10  0.22U_0201_10V6K  [C_0201]  120.26 22.58 180 top
CS11  0.22U_0201_10V6K  [C_0201]  120.18 24.94 180 top
CS12  0.22U_0201_10V6K  [C_0201]  120.18 25.5 180 top
CS13  0.22U_0201_10V6K  [C_0201]  120.15 27.99 180 top
CS14  0.22U_0201_10V6K  [C_0201]  120.15 28.55 180 top
CS32  0.1U_0201_6.3V6K  [C_0201]  25.08 76.68 180 top
CS33  10U_0402_6.3V6M  [C_0402]  25.25 77.53 180 top
CS34  100P_0201_25V8J  [C_0201]  106.73 35.38 90 top
CS35  4.7U_0201_6.3V6M  [C_0201]  55.32 49.71 270 top
CS36  2.2P_0201_25V8C  [C_0201]  59.08 45.86 0 top
CS37  2.2P_0201_25V8C  [C_0201]  57.84 49.74 270 top
CS38  33P_0201_50V8J  [C_0201]  59.08 46.45 0 top
CS39  0.1U_0201_10V6K  [C_0201]  54.74 49.71 270 top
CS41  10P_0201_25V8  [C_0201]  108.41 35.38 90 top
CS42  10U_0402_6.3V6M  [C_0402]  112.17 18.51 0 top
CS43  100P_0201_50V8J  [C_0201]  69.85 76.45 270 top
CS44  0.1U_0201_10V6K  [C_0201]  70.41 76.45 270 top
CS47  27P_0201_25V8  [C_0201]  71.02 76.45 270 top
CS48  0.1U_0201_6.3V6K  [C_0201]  26.36 74.85 270 top
CS49  100P_0201_50V8J  [C_0201]  36.41 68.53 0 bottom
CT1  0.1U_0201_10V6K  [C_0201]  38.7 50.47 0 top
CT2  0.22U_0201_6.3V6K  [C_0201]  19.46 51.07 180 bottom
CT3  0.22U_0201_6.3V6K  [C_0201]  19.46 50.52 180 bottom
CT4  0.22U_0201_6.3V6K  [C_0201]  19.46 53.31 180 bottom
CT5  0.22U_0201_6.3V6K  [C_0201]  19.46 52.75 180 bottom
CT6  0.22U_0201_6.3V6K  [C_0201]  17.35 52.19 0 bottom
CT7  0.22U_0201_6.3V6K  [C_0201]  17.35 51.63 0 bottom
CT8  0.22U_0201_6.3V6K  [C_0201]  17.35 54.43 0 bottom
CT9  0.22U_0201_6.3V6K  [C_0201]  17.35 53.87 0 bottom
CT10  0.1U_0201_10V6K  [C_0201]  29.11 61.75 270 top
CT11  0.1U_0201_10V6K  [C_0201]  29.67 61.75 270 top
CT12  0.1U_0201_10V6K  [C_0201]  30.92 61.75 270 top
CT13  0.1U_0201_10V6K  [C_0201]  30.36 61.75 270 top
CT14  0.1U_0201_10V6K  [C_0201]  33.09 60.17 0 bottom
CT15  0.1U_0201_10V6K  [C_0201]  33.09 60.72 0 bottom
CT16  0.1U_0201_10V6K  [C_0201]  33.08 59.58 0 bottom
CT17  0.1U_0201_10V6K  [C_0201]  33.08 59.02 0 bottom
CT18  0.1U_0201_10V6K  [C_0201]  33.09 55.44 0 bottom
CT19  0.1U_0201_10V6K  [C_0201]  33.09 54.88 0 bottom
CT20  27P_0201_25V8  [C_0201]  18.67 60.74 270 bottom
CT21  27P_0201_25V8  [C_0201]  18.67 61.43 90 bottom
CT67  1U_0201_6.3V6M  [C_0201]  26.82 60.01 90 top
CT68  47U_0603_6.3V6M  [C_0603]  25.34 60.1 90 top
CT69  47U_0603_6.3V6M  [C_0603]  24.15 60.1 90 top
CT95  0.22U_0201_6.3V6K  [C_0201]  19.82 65.9 180 bottom
CT96  0.22U_0201_6.3V6K  [C_0201]  19.82 65.34 180 bottom
CT97  0.22U_0201_6.3V6K  [C_0201]  16.78 65.29 180 bottom
CT98  0.22U_0201_6.3V6K  [C_0201]  16.78 65.85 180 bottom
CT99  0.01U_0201_25V6K  [C_0201]  14.39 61.03 0 top
CT100  0.01U_0201_25V6K  [C_0201]  12.38 70.04 0 top
CT101  0.01U_0201_25V6K  [C_0201]  12.38 69.48 0 top
CT102  0.01U_0201_25V6K  [C_0201]  12.4 70.62 0 top
CT178  0.1U_0201_10V6K  [C_0201]  33.09 56.13 0 bottom
CT179  0.1U_0201_10V6K  [C_0201]  27.02 49.56 270 bottom
CT180  0.1U_0201_10V6K  [C_0201]  27.58 49.56 270 bottom
CT181  0.1U_0201_10V6K  [C_0201]  25.9 49.56 270 bottom
CT182  0.1U_0201_10V6K  [C_0201]  25.34 49.56 270 bottom
CT183  0.1U_0201_10V6K  [C_0201]  28.14 49.56 270 bottom
CT184  0.1U_0201_10V6K  [C_0201]  33.09 56.68 0 bottom
CT185  0.1U_0201_10V6K  [C_0201]  26.46 49.56 270 bottom
CT186  0.1U_0201_10V6K  [C_0201]  28.69 49.56 270 bottom
CT187  0.1U_0201_10V6K  [C_0201]  29.25 49.56 270 bottom
CT189  12P_0201_25V8J  [C_0201]  12.4 71.18 0 top
CT190  82P_0201_25V8J  [C_0201]  14.39 60.47 0 top
CT300  1U_0201_6.3V6M  [C_0201]  21.29 58.47 180 top
CT301  1U_0201_6.3V6M  [C_0201]  23.75 57.77 90 top
CT302  1U_0201_6.3V6M  [C_0201]  21.27 59.05 180 top
CT303  1U_0201_6.3V6M  [C_0201]  23.59 51.67 90 top
CT305  1U_0201_6.3V6M  [C_0201]  26.64 56.91 180 top
CT306  1U_0201_6.3V6M  [C_0201]  26.68 57.58 180 top
CT307  1U_0201_6.3V6M  [C_0201]  25.03 54.37 270 top
CT308  1U_0201_6.3V6M  [C_0201]  25.48 57.57 180 top
CT309  1U_0201_6.3V6M  [C_0201]  26.69 55.58 180 top
CT310  1U_0201_6.3V6M  [C_0201]  24.45 54.37 270 top
CT311  1U_0201_6.3V6M  [C_0201]  26.9 54.41 270 top
CT314  1U_0201_6.3V6M  [C_0201]  20.74 60.07 180 top
CT315  1U_0201_6.3V6M  [C_0201]  20.74 60.63 180 top
CT316  1U_0201_6.3V6M  [C_0201]  24.81 56.9 0 top
CT317  1U_0201_6.3V6M  [C_0201]  24.84 56.23 0 top
CT318  1U_0201_6.3V6M  [C_0201]  26.11 56.24 0 top
CT319  1U_0201_6.3V6M  [C_0201]  25.6 53.81 90 top
CT320  1U_0201_6.3V6M  [C_0201]  24.88 55.57 0 top
CT321  1U_0201_6.3V6M  [C_0201]  26.25 53.83 90 top
CT322  1U_0201_6.3V6M  [C_0201]  27.56 53.82 90 top
CT323  10U_0402_6.3V6M  [C_0402]  25.07 59.2 270 top
CT324  10U_0402_6.3V6M  [C_0402]  26.84 59.2 270 top
CT325  10U_0402_6.3V6M  [C_0402]  27.76 59.2 270 top
CT326  10U_0402_6.3V6M  [C_0402]  25.96 59.2 270 top
CT327  1U_0201_6.3V6M  [C_0201]  26.26 60.01 90 top
CT328  1U_0201_6.3V6M  [C_0201]  27.38 60.02 90 top
CT329  10U_0402_6.3V6M  [C_0402]  28.6 56.13 180 top
CT330  10U_0402_6.3V6M  [C_0402]  28.58 55.24 180 top
CT331  1U_0201_6.3V6M  [C_0201]  29.63 56.54 0 top
CT332  1U_0201_6.3V6M  [C_0201]  28.5 56.87 180 top
CT333  1U_0201_6.3V6M  [C_0201]  27.85 57.59 180 top
CT334  47U_0603_6.3V6M  [C_0603]  26.55 63.88 180 top
CT335  47U_0603_6.3V6M  [C_0603]  28.17 62.77 270 top
CT336  47U_0603_6.3V6M  [C_0603]  26.97 62.77 270 top
CT337  10U_0402_6.3V6M  [C_0402]  21.72 56.71 90 top
CT338  1U_0201_6.3V6M  [C_0201]  23.06 57.03 90 top
CT339  1U_0201_6.3V6M  [C_0201]  23.06 55.78 270 top
CT340  1U_0201_6.3V6M  [C_0201]  22.48 55.78 270 top
CT341  1U_0201_6.3V6M  [C_0201]  22.49 57.02 90 top
CT343  1000P_0201_25V7K  [C_0201]  28.31 30.51 270 top
CT344  100P_0201_50V8J  [C_0201]  29.18 33.84 90 top
CT346  0.022U_0402_25V7K  [C_0402]  29.93 30.79 270 top
CT350  100P_0201_50V8J  [C_0201]  32.31 34.74 180 top
CT351  1000P_0201_25V7K  [C_0201]  33.05 34.77 0 top
CT352  0.022U_0402_25V7K  [C_0402]  32.48 34.01 180 top
CT353  0.22U_0201_6.3V6K  [C_0201]  19.46 54.99 180 bottom
CT354  0.22U_0201_6.3V6K  [C_0201]  19.46 57.78 180 bottom
CT355  0.22U_0201_6.3V6K  [C_0201]  19.46 55.54 180 bottom
CT356  0.22U_0201_6.3V6K  [C_0201]  19.46 57.22 180 bottom
CT357  0.22U_0201_6.3V6K  [C_0201]  17.35 56.66 0 bottom
CT358  0.22U_0201_6.3V6K  [C_0201]  17.35 58.9 0 bottom
CT359  0.22U_0201_6.3V6K  [C_0201]  17.35 56.1 0 bottom
CT360  0.22U_0201_6.3V6K  [C_0201]  17.35 58.34 0 bottom
CT361  0.1U_0201_6.3V6K  [C_0201]  22.15 59.08 270 top
CT362  100P_0201_25V8J  [C_0201]  28.51 59.18 0 top
CT363  0.1U_0201_6.3V6K  [C_0201]  22.16 54.37 270 top
CT364  0.1U_0201_6.3V6K  [C_0201]  22.73 54.37 270 top
CT365  100P_0201_25V8J  [C_0201]  23.88 54.37 270 top
CT366  100P_0201_25V8J  [C_0201]  23.3 54.37 270 top
CT367  0.1U_0201_6.3V6K  [C_0201]  29.07 57.47 90 top
CT368  100P_0201_25V8J  [C_0201]  30.07 57.11 0 top
CT369  100P_0201_25V8J  [C_0201]  28.5 57.47 90 top
CT370  0.1U_0201_6.3V6K  [C_0201]  23.63 56.68 0 top
CT371  100P_0201_25V8J  [C_0201]  23.63 56.11 0 top
CV1  0.22U_0201_6.3V6M  [C_0201]  117.9 53.02 135 bottom
CV2  4.7U_0201_6.3V6M  [C_0201]  113.65 50.54 135 top
CV3  4.7U_0201_6.3V6M  [C_0201]  108.61 51.37 225 top
CV4  0.01U_01005_10V6K  [C_01005]  89.03 68.65 225 bottom
CV5  0.01U_01005_10V6K  [C_01005]  84.96 42.14 90 bottom
CV6  0.22U_0201_6.3V6M  [C_0201]  117.49 52.6 135 bottom
CV7  0.22U_0201_6.3V6M  [C_0201]  117.07 52.19 135 bottom
CV8  0.22U_0201_6.3V6M  [C_0201]  116.66 51.78 135 bottom
CV9  22U_0603_6.3V6M  [C_0603]  110.07 47.79 135 top
CV10  22U_0603_6.3V6M  [C_0603]  111.23 53.14 90 top
CV11  0.22U_0201_6.3V6M  [C_0201]  114.21 49.16 135 bottom
CV12  0.22U_0201_6.3V6M  [C_0201]  114.62 49.57 135 bottom
CV13  0.22U_0201_6.3V6M  [C_0201]  113.38 48.27 135 bottom
CV14  0.22U_0201_6.3V6M  [C_0201]  113.8 48.68 135 bottom
CV15  0.22U_0201_6.3V6M  [C_0201]  112.97 47.83 135 bottom
CV16  0.22U_0201_6.3V6M  [C_0201]  112.56 47.42 135 bottom
CV17  0.22U_0201_6.3V6M  [C_0201]  112.12 47 135 bottom
CV18  0.22U_0201_6.3V6M  [C_0201]  111.7 46.59 135 bottom
CV19  0.22U_0201_6.3V6M  [C_0201]  116.25 51.37 135 bottom
CV20  0.22U_0201_6.3V6M  [C_0201]  115.84 50.96 135 bottom
CV21  0.22U_0201_6.3V6M  [C_0201]  115.41 50.53 135 bottom
CV22  0.22U_0201_6.3V6M  [C_0201]  115 50.13 135 bottom
CV31  0.1U_0201_10V6K  [C_0201]  105.78 65.85 45 top
CV34  0.1U_0201_10V6K  [C_0201]  104.22 65.18 135 top
CV38  1U_0201_6.3V6M  [C_0201]  103.43 48.61 45 top
CV44  10U_0603_6.3V6M  [C_0603]  99.04 35.82 180 top
CV45  22U_0603_6.3V6M  [C_0603]  99.04 34.62 180 top
CV51  22U_0603_6.3V6M  [C_0603]  99.03 52.74 270 top
CV52  0.1U_0201_10V6K  [C_0201]  97.65 54.98 0 top
CV53  0.1U_0201_10V6K  [C_0201]  98.81 54.43 90 top
CV55  0.1U_0201_10V6K  [C_0201]  104.39 63.47 270 top
CV60  0.1U_0201_10V6K  [C_0201]  104.59 67.06 45 top
CV75  47P_0201_25V8J  [C_0201]  44.86 65.99 0 top
CV76  100P_0201_25V7K  [C_0201]  44.86 65.43 0 top
CV77  0.1U_0201_25V6K  [C_0201]  44.86 66.55 0 top
CV158  820P_0201_25V7K  [C_0201]  92.88 64.58 270 top
CV159  820P_0201_25V7K  [C_0201]  93.46 64.59 270 top
CV196  0.047U_0201_6.3V6K  [C_0201]  114.22 45.19 315 top
CV197  2200P_0201_16V7K  [C_0201]  119 44.58 135 top
CV198  10U_0402_6.3V6M  [C_0402]  106.56 50.8 315 top
CV199  10U_0603_6.3V6M  [C_0603]  110.95 48.63 135 top
CV200  1U_0201_6.3V6M  [C_0201]  111.39 52.24 315 top
CV201  1U_0201_6.3V6M  [C_0201]  107 51.49 315 top
CV202  1U_0201_6.3V6M  [C_0201]  109.05 47.46 135 top
CV203  10U_0402_6.3V6M  [C_0402]  105.9 50.12 315 top
CV204  10U_0603_6.3V6M  [C_0603]  111.8 49.47 135 top
CV205  4.7U_0201_6.3V6M  [C_0201]  114.05 50.95 135 top
CV206  0.1U_0201_6.3V6K  [C_0201]  119.97 46.12 270 top
CV207  0.1U_0201_6.3V6K  [C_0201]  112.71 54.71 180 top
CV209  15P_0201_25V8J  [C_0201]  97.64 73.96 180 bottom
CV210  15P_0201_25V8J  [C_0201]  95.87 73.97 0 bottom
CV211  0.1U_0201_10V6K  [C_0201]  103.45 67.9 90 top
CV212  1U_0201_6.3V6M  [C_0201]  98.28 68.13 180 top
CV213  4.7U_0201_6.3V6M  [C_0201]  98.28 68.71 180 top
CV214  0.1U_0201_10V6K  [C_0201]  99.27 63.86 225 top
CV216  4.7U_0201_6.3V6M  [C_0201]  102.07 65.14 315 top
CV217  1U_0201_6.3V6M  [C_0201]  96.97 62.66 180 top
CV218  1U_0201_6.3V6M  [C_0201]  92.37 62.77 180 top
CV219  1U_0201_6.3V6M  [C_0201]  101.75 67.9 90 top
CV220  0.1U_0201_10V6K  [C_0201]  102.31 67.9 90 top
CV221  1U_0201_6.3V6M  [C_0201]  98.21 62.71 0 top
CV222  1U_0201_6.3V6M  [C_0201]  114.87 51.78 135 top
CV322  1U_0201_6.3V6M  [C_0201]  118.45 47.58 180 top
CV323  1U_0201_6.3V6M  [C_0201]  120.78 50.46 90 top
CV324  0.1U_0201_6.3V6K  [C_0201]  115.56 51.93 270 top
CV325  0.1U_0201_6.3V6K  [C_0201]  120.06 55.54 0 top
CV326  220P_0201_25V7K  [C_0201]  118.38 53.18 180 top
